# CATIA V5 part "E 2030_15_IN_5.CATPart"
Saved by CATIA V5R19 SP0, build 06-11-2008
Material "Plastic": density 1200 kg/m3, Young's modulus 2.2e+09 Pa, Poisson ratio 0.38, thermal expansion 6.84e-05 1/K
Bounding box of the stored display mesh (mm): x -7.55 to 7.55, y -30.19 to -15.11, z -2 to 0
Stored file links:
  G:\UTB\Kombinované\Bakalářská práce\Catia\FORMA\E 2030_15_IN_5.CATPart
  D:\Aplikace\CATIA\Nová složka\win_b64\startup\materials\Catalog.CATMaterial
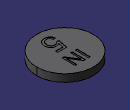
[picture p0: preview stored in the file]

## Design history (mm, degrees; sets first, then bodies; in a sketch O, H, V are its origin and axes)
Body1 "E 2030_15_IN_1-8" (main body)
  Solid1: solid without history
